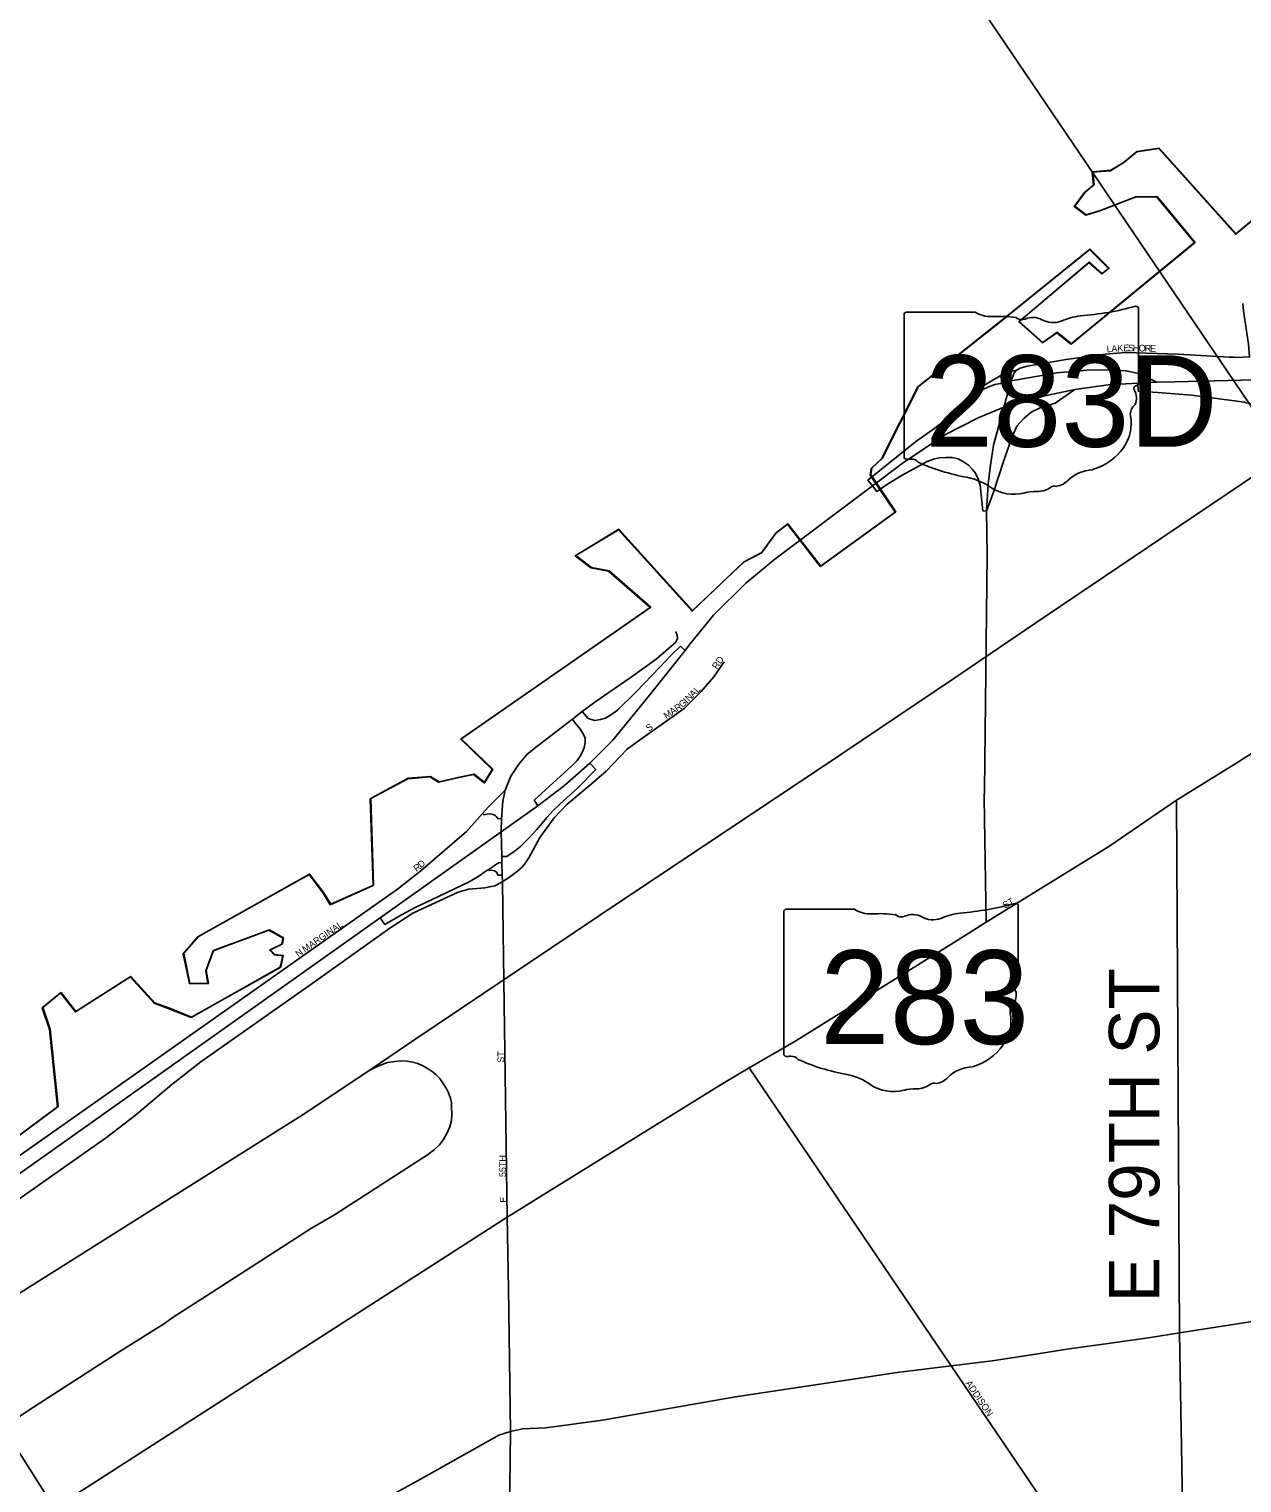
# Model space of a CAD drawing. Extents: x 2139079 to 2262683, y 1235796 to 1334992.
# Drawn here: x 2197328 to 2206334, y 1282328 to 1293125 of the extents above; entities that cross this region are included whole.
import ezdxf

# ---------------------------------------------------------------- set-up
doc = ezdxf.new("R2010")
doc.units = 0
for name, color, linetype in [('GM_X_City_Street', 7, 'Continuous'), ('GM_X_City_Street_Text', 7, 'Continuous'), ('GM_X_Interchange_Ramps', 7, 'Continuous'), ('GM_X_Interstate_Route', 7, 'Continuous'), ('GM_X_Major_Lake', 7, 'Continuous'), ('GM_X_Major_River', 7, 'Continuous'), ('GM_X_Rail_Line', 7, 'Continuous'), ('GM_X_State_Location', 7, 'Continuous'), ('GM_X_State_Route', 7, 'Continuous'), ('GM_X_State_Shield', 7, 'Continuous'), ('GM_X_US_Route', 7, 'Continuous')]:
    doc.layers.add(name, color=color, linetype=linetype)

msp = doc.modelspace()

# ---------------------------------------------------------------- linework, layer by layer
at = {"layer": 'GM_X_City_Street'}
for points in [[(2206277, 1290688), (2206298, 1290687), (2206391, 1290690), (2206382, 1290786), (2206346, 1291033), (2206341, 1291086)], [(2204659, 1290593), (2204687, 1290607), (2204740, 1290621), (2205028, 1290672), (2205318, 1290711), (2205469, 1290722), (2205861, 1290711), (2206239, 1290689), (2206277, 1290688)], [(2204620, 1290513), (2204642, 1290571), (2204659, 1290593)], [(2201520, 1288119), (2201593, 1288172), (2201791, 1288306), (2201985, 1288446), (2202127, 1288570), (2202143, 1288596), (2202141, 1288626), (2202127, 1288650)], [(2201844, 1287831), (2202192, 1288079), (2202316, 1288203), (2202413, 1288315), (2202489, 1288426)], [(2201434, 1288057), (2201520, 1288119)], [(2200864, 1287472), (2200905, 1287576), (2200964, 1287667), (2201026, 1287739), (2201099, 1287796), (2201362, 1288000)], [(2201362, 1288000), (2201434, 1288057)], [(2200843, 1286792), (2200905, 1286835), (2200955, 1286870), (2200992, 1286904), (2201015, 1286933), (2201039, 1286971), (2201121, 1287121), (2201226, 1287266), (2201321, 1287367), (2201486, 1287504), (2201614, 1287614), (2201768, 1287777), (2201844, 1287831)], [(2206330, 1287697), (2206337, 1287702), (2206633, 1287884), (2206638, 1287887)], [(2204434, 1286492), (2205346, 1287055), (2205847, 1287398), (2206327, 1287695), (2206330, 1287697)], [(2200864, 1287472), (2200738, 1287347), (2200696, 1287299), (2200576, 1287165), (2200238, 1286873), (2200064, 1286738), (2198074, 1285333), (2195559, 1283563)], [(2200839, 1286935), (2200838, 1286979), (2200834, 1287163), (2200837, 1287261), (2200846, 1287391), (2200864, 1287472)], [(2205870, 1283443), (2205847, 1287398)], [(2200848, 1286410), (2200843, 1286792), (2200842, 1286842), (2200839, 1286935)], [(2196407, 1283843), (2197904, 1284894), (2198118, 1285059), (2198388, 1285286), (2198604, 1285454), (2199455, 1286053), (2200007, 1286449), (2200177, 1286560), (2200514, 1286716), (2200594, 1286738), (2200712, 1286747), (2200787, 1286761), (2200843, 1286792)], [(2200878, 1284302), (2200848, 1286410)], [(2205919, 1280629), (2205000, 1281983), (2204176, 1283198), (2202675, 1285411)], [(2195567, 1280882), (2195932, 1281122), (2196014, 1281175), (2197516, 1282141), (2200878, 1284302)], [(2199693, 1274636), (2199757, 1274882), (2199488, 1276121), (2199424, 1276515), (2199347, 1276984), (2199267, 1277477), (2199159, 1278137), (2199026, 1278951), (2198913, 1279951), (2198889, 1280010), (2198106, 1281211), (2197516, 1282141), (2197025, 1282916), (2196407, 1283843)], [(2205880, 1282863), (2205870, 1283443)], [(2205884, 1282600), (2205880, 1282863), (2205880, 1282863)], [(2200960, 1276773), (2200948, 1277712), (2200932, 1278401), (2200914, 1279221), (2200892, 1280177), (2200883, 1280550), (2200880, 1280784), (2200880, 1280871), (2200904, 1282710)], [(2205916, 1280756), (2205895, 1281994), (2205884, 1282600), (2205884, 1282600)]]:
    msp.add_lwpolyline(points, dxfattribs=at)
at = {"layer": 'GM_X_Interchange_Ramps'}
for points in [[(2204659, 1290593), (2204597, 1290577), (2204538, 1290549), (2204431, 1290486), (2204384, 1290455), (2204329, 1290412), (2204311, 1290395), (2204156, 1290245), (2204113, 1290207), (2204054, 1290162), (2203911, 1290059), (2203557, 1289776), (2203591, 1289733)], [(2204620, 1290513), (2204572, 1290503), (2204540, 1290494), (2204498, 1290486), (2204446, 1290465), (2204400, 1290443), (2204369, 1290426), (2204319, 1290387), (2204311, 1290395)], [(2205560, 1290495), (2205563, 1290437), (2205710, 1290425), (2205960, 1290405), (2206354, 1290353), (2206358, 1290352), (2206389, 1290344), (2206403, 1290339), (2206414, 1290329), (2206431, 1290309), (2206443, 1290287), (2206470, 1290294)], [(2203591, 1289733), (2203624, 1289690), (2203709, 1289750), (2203815, 1289814), (2203997, 1289913), (2204044, 1289930), (2204086, 1289941), (2204135, 1289944), (2204182, 1289943), (2204227, 1289933), (2204266, 1289912), (2204303, 1289886), (2204332, 1289856), (2204355, 1289827), (2204374, 1289789), (2204391, 1289739), (2204411, 1289546), (2204437, 1289545)], [(2202199, 1288511), (2202165, 1288541), (2202096, 1288476), (2202012, 1288386), (2201836, 1288204), (2201697, 1288068), (2201645, 1288029), (2201608, 1288008), (2201572, 1287997), (2201529, 1287991), (2201495, 1287999), (2201478, 1288008), (2201453, 1288036), (2201434, 1288057)], [(2201362, 1288000), (2201379, 1287978), (2201422, 1287924), (2201442, 1287891), (2201457, 1287858), (2201457, 1287824), (2201451, 1287789), (2201438, 1287757), (2201421, 1287725), (2201398, 1287694), (2201358, 1287654), (2201079, 1287399), (2201107, 1287356)], [(2200838, 1286979), (2200875, 1286979), (2200931, 1287018), (2200980, 1287057), (2201035, 1287111), (2201099, 1287180), (2201174, 1287273), (2201216, 1287319), (2201268, 1287368), (2201401, 1287487), (2201536, 1287626), (2201491, 1287673)], [(2200696, 1287299), (2200707, 1287289), (2200728, 1287295), (2200753, 1287296), (2200774, 1287291), (2200788, 1287284), (2200798, 1287275), (2200808, 1287262), (2200837, 1287261)], [(2199935, 1286525), (2199970, 1286474), (2200093, 1286547), (2200206, 1286607), (2200322, 1286661), (2200595, 1286793), (2200667, 1286834), (2200715, 1286868), (2200736, 1286881), (2200781, 1286911), (2200813, 1286934), (2200839, 1286935)], [(2200736, 1286881), (2200740, 1286876), (2200763, 1286878), (2200783, 1286874), (2200799, 1286864), (2200805, 1286856), (2200808, 1286842), (2200842, 1286842)]]:
    msp.add_lwpolyline(points, dxfattribs=at)
at = {"layer": 'GM_X_Interstate_Route'}
for points in [[(2196858, 1284615), (2197540, 1285121), (2197479, 1285695), (2197426, 1285857), (2197561, 1285967), (2197672, 1285826), (2198079, 1286087), (2198257, 1285891), (2198380, 1285845), (2198531, 1285785), (2199193, 1286157), (2199212, 1286243), (2199148, 1286250), (2199115, 1286284), (2199205, 1286329), (2199214, 1286374), (2199109, 1286432), (2198694, 1286279), (2198640, 1286130), (2198655, 1286036), (2198519, 1286036), (2198473, 1286258), (2198582, 1286384), (2199407, 1286846), (2199512, 1286708), (2199565, 1286622), (2199882, 1286765), (2199862, 1287408), (2200140, 1287558), (2200304, 1287571), (2200367, 1287532), (2200531, 1287568), (2200629, 1287590), (2200708, 1287527), (2200767, 1287626), (2200533, 1287851), (2201940, 1288829), (2201630, 1289099), (2201500, 1289123), (2201384, 1289214), (2201704, 1289407), (2202251, 1288803), (2202632, 1289166), (2202766, 1289235), (2202872, 1289381), (2202959, 1289449), (2203203, 1289133), (2203760, 1289537), (2203573, 1289813), (2203581, 1289861), (2203658, 1289934), (2203928, 1290468), (2204599, 1291001), (2205202, 1291489), (2205342, 1291346), (2205293, 1291307), (2205197, 1291392), (2204677, 1290950), (2204852, 1290795), (2204959, 1290870), (2205064, 1290786), (2205981, 1291539), (2205699, 1291880), (2205541, 1291877), (2205279, 1291775), (2205174, 1291743), (2205088, 1291808), (2205165, 1291912), (2205232, 1291967), (2205223, 1292063), (2205357, 1292073), (2205452, 1292131), (2205551, 1292213), (2205716, 1292237), (2206285, 1291601), (2206599, 1291862)], [(2205094, 1290448), (2205341, 1290483), (2205560, 1290495), (2205703, 1290503), (2205835, 1290506)], [(2205835, 1290506), (2206424, 1290519)], [(2200834, 1287163), (2201107, 1287356), (2201303, 1287507), (2201491, 1287673), (2201662, 1287844), (2201936, 1288177), (2202199, 1288511), (2202235, 1288558), (2202409, 1288773), (2202650, 1289011), (2202865, 1289189), (2203591, 1289733), (2203810, 1289898), (2204129, 1290112), (2204375, 1290239), (2204566, 1290318), (2204807, 1290388), (2204836, 1290394)], [(2204836, 1290394), (2205094, 1290448)], [(2200234, 1286738), (2200834, 1287163)], [(2196450, 1284054), (2199935, 1286525), (2200234, 1286738)]]:
    msp.add_lwpolyline(points, dxfattribs=at)
at = {"layer": 'GM_X_Major_Lake'}
for points in [[(2206290, 1291604), (2206603, 1291864), (2206695, 1291901), (2206874, 1291882), (2207030, 1291890), (2207174, 1292005), (2207319, 1292119), (2207432, 1292237), (2207583, 1292382), (2207713, 1292484), (2207833, 1292511), (2207950, 1292636), (2208038, 1292731), (2208175, 1292835)], [(2204604, 1291004), (2205206, 1291491), (2205347, 1291349), (2205297, 1291310), (2205202, 1291395), (2204681, 1290953), (2204856, 1290797), (2204963, 1290873), (2205069, 1290788), (2205986, 1291541), (2205704, 1291882), (2205545, 1291880), (2205284, 1291778), (2205178, 1291746), (2205093, 1291811), (2205169, 1291914), (2205237, 1291970), (2205227, 1292066), (2205361, 1292076), (2205457, 1292134), (2205556, 1292215), (2205720, 1292240), (2206290, 1291604)], [(2204604, 1291004), (2205206, 1291491), (2205347, 1291349), (2205297, 1291310), (2205202, 1291395), (2204681, 1290953), (2204856, 1290797), (2204963, 1290873), (2205069, 1290788), (2205986, 1291541), (2205704, 1291882), (2205545, 1291880), (2205284, 1291778), (2205178, 1291746), (2205093, 1291811), (2205169, 1291914), (2205237, 1291970), (2205227, 1292066), (2205361, 1292076), (2205457, 1292134), (2205556, 1292215), (2205720, 1292240), (2206290, 1291604)], [(2203585, 1289863), (2203663, 1289936), (2203933, 1290470), (2204604, 1291004)], [(2203585, 1289863), (2203663, 1289936), (2203933, 1290470), (2204592, 1290994)], [(2196863, 1284618), (2197545, 1285124), (2197484, 1285697), (2197431, 1285859), (2197566, 1285970), (2197676, 1285829), (2198083, 1286090), (2198261, 1285894), (2198384, 1285848), (2198535, 1285788), (2199198, 1286159), (2199216, 1286246), (2199152, 1286253), (2199119, 1286286), (2199209, 1286332), (2199218, 1286376), (2199113, 1286435), (2198698, 1286282), (2198644, 1286133), (2198660, 1286038), (2198523, 1286038), (2198478, 1286261), (2198586, 1286387), (2199411, 1286849), (2199516, 1286710), (2199569, 1286625), (2199886, 1286768), (2199866, 1287410), (2200144, 1287561), (2200309, 1287574), (2200372, 1287534), (2200536, 1287571), (2200633, 1287592), (2200713, 1287529), (2200771, 1287629), (2200537, 1287854), (2201944, 1288831), (2201635, 1289102), (2201504, 1289126), (2201388, 1289216), (2201708, 1289410), (2202255, 1288806), (2202637, 1289169), (2202770, 1289237), (2202876, 1289384), (2202963, 1289451), (2203207, 1289136), (2203764, 1289540), (2203578, 1289816), (2203585, 1289863)], [(2196863, 1284618), (2197545, 1285124), (2197484, 1285697), (2197431, 1285859), (2197566, 1285970), (2197676, 1285829), (2198083, 1286090), (2198261, 1285894), (2198384, 1285848), (2198535, 1285788), (2199198, 1286159), (2199216, 1286246), (2199152, 1286253), (2199119, 1286286), (2199209, 1286332), (2199218, 1286376), (2199113, 1286435), (2198698, 1286282), (2198644, 1286133), (2198660, 1286038), (2198523, 1286038), (2198478, 1286261), (2198586, 1286387), (2199411, 1286849), (2199516, 1286710), (2199569, 1286625), (2199886, 1286768), (2199866, 1287410), (2200144, 1287561), (2200309, 1287574), (2200372, 1287534), (2200536, 1287571), (2200633, 1287592), (2200713, 1287529), (2200771, 1287629), (2200537, 1287854), (2201944, 1288831), (2201635, 1289102), (2201504, 1289126), (2201388, 1289216), (2201708, 1289410), (2202255, 1288806), (2202637, 1289169), (2202770, 1289237), (2202876, 1289384), (2202963, 1289451), (2203207, 1289136), (2203764, 1289540), (2203578, 1289816), (2203585, 1289863)], [(2196863, 1284618), (2197545, 1285124), (2197484, 1285697), (2197431, 1285859), (2197566, 1285970), (2197676, 1285829), (2198083, 1286090), (2198261, 1285894), (2198384, 1285848), (2198535, 1285788), (2199198, 1286159), (2199216, 1286246), (2199152, 1286253), (2199119, 1286286), (2199209, 1286332), (2199218, 1286376), (2199113, 1286435), (2198698, 1286282), (2198644, 1286133), (2198660, 1286038), (2198523, 1286038), (2198478, 1286261), (2198586, 1286387), (2199411, 1286849), (2199516, 1286710), (2199569, 1286625), (2199886, 1286768), (2199866, 1287410), (2200144, 1287561), (2200309, 1287574), (2200372, 1287534), (2200536, 1287571), (2200633, 1287592), (2200713, 1287529), (2200771, 1287629), (2200537, 1287854), (2201944, 1288831), (2201635, 1289102), (2201504, 1289126), (2201388, 1289216), (2201708, 1289410), (2202255, 1288806), (2202637, 1289169), (2202770, 1289237), (2202876, 1289384), (2202963, 1289451), (2203207, 1289136), (2203764, 1289540), (2203578, 1289816), (2203585, 1289863)]]:
    msp.add_lwpolyline(points, dxfattribs=at)
at = {"layer": 'GM_X_Major_River'}
msp.add_lwpolyline([(2204604, 1291004), (2205206, 1291491), (2205347, 1291349), (2205297, 1291310), (2205202, 1291395), (2204681, 1290953), (2204856, 1290797), (2204963, 1290873), (2205069, 1290788), (2205986, 1291541), (2205704, 1291882), (2205545, 1291880), (2205284, 1291778), (2205178, 1291746), (2205093, 1291811), (2205169, 1291914), (2205237, 1291970), (2205227, 1292066), (2205361, 1292076), (2205457, 1292134), (2205556, 1292215), (2205720, 1292240), (2206290, 1291604)], dxfattribs=at)
at = {"layer": 'GM_X_Rail_Line'}
for points in [[(2203228, 1287651), (2204195, 1288303), (2204797, 1288710), (2205632, 1289275), (2206337, 1289751), (2206850, 1290099), (2207481, 1290525), (2207992, 1290872), (2208474, 1291197), (2209456, 1291861), (2209862, 1292136), (2210354, 1292453), (2211370, 1293079), (2212078, 1293511), (2212987, 1294057), (2214202, 1294796), (2216245, 1296040), (2216687, 1296308), (2217206, 1296625), (2218315, 1297299)], [(2200200, 1285625), (2201723, 1286649), (2203228, 1287651)], [(2199861, 1285395), (2200200, 1285625)], [(2199861, 1285395), (2199937, 1285431), (2199990, 1285449), (2200043, 1285458), (2200093, 1285462), (2200135, 1285460), (2200175, 1285452), (2200215, 1285442), (2200253, 1285426), (2200292, 1285403), (2200320, 1285384), (2200351, 1285359), (2200378, 1285331), (2200404, 1285295)], [(2188799, 1277975), (2189752, 1278589), (2190640, 1279116), (2192678, 1280555), (2194232, 1281639), (2194949, 1282155), (2195509, 1282554), (2195872, 1282810), (2196379, 1283156), (2197087, 1283630), (2199384, 1285076), (2199861, 1285395)], [(2196761, 1282495), (2197362, 1282890), (2198010, 1283308), (2198334, 1283512), (2198397, 1283558), (2198646, 1283717), (2199425, 1284220), (2199595, 1284318), (2200286, 1284765), (2200338, 1284805), (2200376, 1284839), (2200406, 1284879), (2200431, 1284923), (2200452, 1284972), (2200464, 1285020), (2200466, 1285070), (2200465, 1285115), (2200465, 1285151), (2200458, 1285185), (2200443, 1285224), (2200426, 1285259), (2200404, 1285295)]]:
    msp.add_lwpolyline(points, dxfattribs=at)
at = {"layer": 'GM_X_State_Route'}
for points in [[(2205703, 1290503), (2205569, 1290568), (2205473, 1290588), (2205347, 1290594), (2205182, 1290592), (2204960, 1290571), (2204620, 1290513)], [(2204620, 1290513), (2204612, 1290482), (2204588, 1290396)], [(2204437, 1289545), (2204491, 1289694), (2204564, 1289914), (2204625, 1290093), (2204663, 1290175), (2204714, 1290234), (2204768, 1290281), (2204836, 1290313), (2204946, 1290347), (2205094, 1290448)], [(2204588, 1290396), (2204566, 1290318), (2204526, 1290172), (2204490, 1290034), (2204466, 1289886), (2204449, 1289746), (2204437, 1289545)], [(2204422, 1287477), (2204426, 1287686), (2204443, 1289222), (2204437, 1289545)], [(2204434, 1286492), (2204420, 1287413), (2204422, 1287477)], [(2200878, 1284302), (2202466, 1285286), (2202675, 1285411), (2203008, 1285604), (2204219, 1286357), (2204434, 1286492)], [(2200887, 1283771), (2200878, 1284302)], [(2200904, 1282710), (2200887, 1283771)]]:
    msp.add_lwpolyline(points, dxfattribs=at)
at = {"layer": 'GM_X_State_Shield'}
for p, q in [((2204353, 1291023), (2203843, 1291023)), ((2205566, 1290496), (2205566, 1291049)), ((2203826, 1291005), (2203826, 1289948)), ((2205566, 1290496), (2205566, 1290496)), ((2204673, 1286061), (2204673, 1286614)), ((2202933, 1286569), (2202933, 1285513)), ((2203460, 1286588), (2202950, 1286588)), ((2204673, 1286061), (2204673, 1286061))]:
    msp.add_line(p, q, dxfattribs=at)
for centre, major_axis, start_param, end_param in [((2203846, 1291007), (20.2, 0), 1.712693, 3.28349), ((2204474, 1291146), (196, 0), 4.042523, 4.731795), ((2204947, 1292463), (1845, 0), 4.814394, 5.042369), ((2205547, 1291051), (19.4, 0), 6.141152, 7.989035), ((2204539, 1290430), (702, 0), 1.404758, 1.657858), ((2204699, 1291012), (56.4, 0), 3.836095, 5.185415), ((2204781, 1290890), (117, 0), 0.950623, 2.079405), ((2204933, 1291058), (141, 0), 4.081561, 5.145723), ((2205182, 1290700), (371, 0), 1.699011, 2.107814), ((2205546, 1290494), (20.7, 0), 5.05454, 6.418171), ((2205562, 1290456), (30, 0), 1.883978, 3.671073), ((2205371, 1290386), (180, 0), 5.934695, 6.695948), ((2205636, 1290265), (131, 0), 2.387724, 3.262537), ((2205050, 1290195), (462, 0), 5.101752, 6.440018), ((2203846, 1289946), (20.3, 0), 3.00124, 4.508301), ((2203849, 1290054), (155, 0), 4.665946, 4.897461), ((2203881, 1289887), (56, 0), 0.519207, 1.627899), ((2204588, 1290836), (1333, 0), 4.195997, 4.488961), ((2205245, 1289651), (253, 0), 1.647645, 2.488434), ((2204190, 1289473), (417, 0), 0.823519, 1.323587), ((2204941, 1289700), (39.7, 0), 1.147584, 2.315152), ((2204924, 1289846), (149, 0), 4.937069, 5.64225), ((2204641, 1289882), (265, 0), 4.026481, 4.996735), ((2204794, 1289517), (217, 0), 1.495662, 1.94098), ((2204814, 1289803), (141, 0), 4.691044, 5.507374), ((2204053, 1288028), (1845, 0), 4.814394, 5.042369), ((2204654, 1286616), (19.4, 0), 6.141152, 7.989035), ((2202953, 1286572), (20.2, 0), 1.712693, 3.28349), ((2203581, 1286710), (196, 0), 4.042523, 4.731795), ((2203646, 1285994), (702, 0), 1.404758, 1.657858), ((2203805, 1286577), (56.4, 0), 3.836095, 5.185415), ((2203888, 1286455), (117, 0), 0.950623, 2.079405), ((2204040, 1286623), (141, 0), 4.081561, 5.145723), ((2204289, 1286265), (371, 0), 1.699011, 2.107814), ((2204653, 1286059), (20.7, 0), 5.05454, 6.418171), ((2204669, 1286021), (30, 0), 1.883978, 3.671073), ((2204478, 1285951), (180, 0), 5.934695, 6.695948), ((2204743, 1285830), (131, 0), 2.387724, 3.262537), ((2204157, 1285759), (462, 0), 5.101752, 6.440018), ((2202953, 1285511), (20.3, 0), 3.00124, 4.508301), ((2202956, 1285619), (155, 0), 4.665946, 4.897461), ((2202988, 1285452), (56, 0), 0.519207, 1.627899), ((2203695, 1286401), (1333, 0), 4.195997, 4.488961), ((2204351, 1285216), (253, 0), 1.647645, 2.488434), ((2203297, 1285038), (417, 0), 0.823519, 1.323587), ((2204048, 1285265), (39.7, 0), 1.147584, 2.315152), ((2204031, 1285410), (149, 0), 4.937069, 5.64225), ((2203748, 1285447), (265, 0), 4.026481, 4.996735), ((2203901, 1285081), (217, 0), 1.495662, 1.94098), ((2203920, 1285368), (141, 0), 4.691044, 5.507374)]:
    msp.add_ellipse(centre, major_axis=major_axis, ratio=0.8, start_param=start_param, end_param=end_param, dxfattribs=at)
at = {"layer": 'GM_X_US_Route'}
msp.add_lwpolyline([(2202868, 1295541), (2210354, 1284489), (2249318, 1310882), (2241832, 1321934)], close=True, dxfattribs=at)
for points in [[(2200904, 1282710), (2200991, 1282729), (2201165, 1282737), (2201585, 1282795), (2202574, 1282967), (2203431, 1283095), (2203775, 1283148), (2204176, 1283198), (2204480, 1283235), (2204772, 1283280), (2205050, 1283323), (2205340, 1283364), (2205656, 1283409), (2205870, 1283443), (2208927, 1283918)], [(2195311, 1279717), (2195407, 1279771), (2195541, 1279844), (2195772, 1279968), (2198106, 1281211), (2199509, 1281962), (2199732, 1282083), (2199981, 1282217), (2200240, 1282358), (2200817, 1282683), (2200904, 1282710)]]:
    msp.add_lwpolyline(points, dxfattribs=at)

# ---------------------------------------------------------------- texts
at = {"layer": 'GM_X_City_Street_Text'}
for s, height, rotation, p in [('L', 50, 3.636, (2205331, 1290724)), ('A', 50, 3.6479, (2205366, 1290726)), ('K', 50, 3.5436, (2205410, 1290729)), ('E', 50, 1.0108, (2205453, 1290732)), ('S', 50, 359.0711, (2205488, 1290732)), ('H', 50, 358.8853, (2205523, 1290732)), ('O', 50, 358.9118, (2205567, 1290731)), ('R', 50, 358.9072, (2205611, 1290730)), ('E', 50, 358.9146, (2205651, 1290729)), ('RD', 50, 56.3133, (2202437, 1288366)), ('A', 50, 45.047, (2202260, 1288159)), ('L', 50, 46.768, (2202293, 1288191)), ('R', 50, 34.7899, (2202141, 1288054)), ('G', 50, 41.6392, (2202179, 1288081)), ('I', 50, 44.9085, (2202214, 1288112)), ('N', 50, 45.047, (2202229, 1288128)), ('M', 50, 34.6802, (2202061, 1287999)), ('A', 50, 34.6987, (2202105, 1288029)), ('S', 50, 33.6985, (2201929, 1287906)), ('R', 50, 36.5737, (2200205, 1286864)), ('D', 50, 41.4434, (2200240, 1286891)), ('ST', 50, 29.7432, (2204574, 1286591)), ('MARGINAL', 50, 34.745, (2199377, 1286265)), ('N', 50, 36.8743, (2199329, 1286230)), ('E 79TH ST', 375, 90, (2205721, 1283670)), ('ST', 50, 90, (2200856, 1285448)), ('55TH', 50, 90, (2200869, 1284599)), ('E', 50, 90, (2200874, 1284409)), ('ADDISON', 50, 303.9425, (2204279, 1283068))]:
    msp.add_text(s, height=height, rotation=rotation, dxfattribs=at).set_placement(p)
at = {"layer": 'GM_X_State_Location'}
for s, p in [('s', (2204677, 1290406)), ('r', (2204677, 1290406)), ('s', (2203784, 1285971)), ('r', (2203784, 1285971))]:
    msp.add_text(s, height=1, dxfattribs=at).set_placement(p)
for s, p in [('283D', (2204253, 1290362)), ('283', (2203431, 1285898))]:
    msp.add_text(s, height=1, rotation=0, dxfattribs=at).set_placement(p)
at = {"layer": 'GM_X_State_Shield'}
for s, height, p in [('283D', 680, (2203981, 1290023)), ('283', 696.1, (2203201, 1285587))]:
    msp.add_text(s, height=height, dxfattribs=at).set_placement(p)

doc.saveas('drawing.dxf')
